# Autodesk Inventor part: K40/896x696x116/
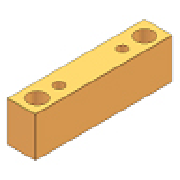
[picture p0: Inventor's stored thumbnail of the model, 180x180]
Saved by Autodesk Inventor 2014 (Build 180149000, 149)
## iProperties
Created: 2009-11
Part Number: K40/896x696x116/
Material: DIN 1.1730
Description: Spacer Block
Document SubType Name: Modeling
Designer: gaom
Standard Revision: 1
Manufacturer: HASCO
Language: en-US
Size Designation: 896x696x116/
Categories: <MemberInstance><Categories><Category DisplayName="Mold" InternalName="349578f2-f4d4-4954-8c09-8e99297a61c0" Mnemonic="MOLD"><Category DisplayName="Mold Plates"
Density: 7.82 g/cm^3
Appearance: Orange (Pale)
IsCustomPart: 1
Author: gaom
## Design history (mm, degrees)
sketch "Sketch1"
  geometry: L1 (-264, 448)-(-348, 448); L2 (-348, 448)-(-348, -448); L3 (-348, -448)-(-264, -448); L4 (-264, -448)-(-264, 448); L5 (348, 448)-(348, -448); L6 (264, -448)-(264, 448); L7 (264, 448)-(348, 448); L8 (264, -448)-(348, -448); 7 further points
  constraints: 16 end point, 3 parallel, 2 horizontal alignment, 2 midpoint, 2 perpendicular, 1 horizontal, 1 vertical
  dimensions: "d85" = 896 distance between parallel lines of L3 L1 (= L); "d86" = 84 distance between parallel lines of L4 L2 (= W_); "d88" = 84 distance between parallel lines of L5 L6 (= W_); "d89" = 348 distance from line of point (0, 0) L2 (= 0.5 x M_W); "d93" = 896 distance between parallel lines of L8 L7 (= L); "d94" = 348 distance from line of point (0, 0) L5 (= 0.5 x M_W); "d98" = 337 vertical distance of point (-296, 337) point (0, 0) (= 0.5 x S1_L); "d100" = 296 horizontal distance of point (-296, 337) point (0, 0) (= 0.5 x S1_W); "d101" = 296 horizontal distance of point (296, 337) point (0, 0) (= 0.5 x S1_W); "d102" = 337 vertical distance of point (0, 0) point (296, 337) (= 0.5 x S1_L); "d103" = 296 horizontal distance of point (-296, 396) point (0, 0) (= 0.5 x LS_W); "d105" = 396 vertical distance of point (-296, 396) point (0, 0) (= 0.5 x LS_L); "d106" = 296 horizontal distance of point (0, 0) point (296, 396) (= 0.5 x LS_W); "d107" = 396 vertical distance of point (296, 396) point (0, 0) (= 0.5 x LS_L)
extrude "Extrusion1" new body sketch "Sketch1" distance "d20" = 116 (= H_); taper "d30" = 0 deg
extrude "Extrusion2" join sketch "Sketch1" distance "d95" = 116 (= H_); taper "d96" = 0 deg
body "Solid1"
hole "Hole1" sketch "Sketch1" diameter "d129" = 22 (= S1_d1); stored, may be unused: countersink angle "d133" = 90 deg, drill point angle "d135" = 0 deg; dims "d130" = 6, "d131" = 4, "d132" = 2, "d134" = 116 (= H_)
pattern_linear "Rectangular Pattern1" dims "d156" = 674 (computed from S1_L, Ns)
hole "Hole2" sketch "Sketch1" diameter "d108" = 54 (= LS_d); stored, may be unused: countersink angle "d112" = 90 deg, drill point angle "d114" = 0 deg; dims "d109" = 6, "d110" = 4, "d111" = 2, "d113" = 116 (= H_)
pattern_linear "Rectangular Pattern2" dims "d138" = 792 (computed from LS_L, Nl)
hole "Hole3" sketch "Sketch1" diameter "d122" = 22 (= S1_d1); stored, may be unused: countersink angle "d126" = 90 deg, drill point angle "d128" = 0 deg; dims "d123" = 6, "d124" = 4, "d125" = 2, "d127" = 116 (= H_)
pattern_linear "Rectangular Pattern3" dims "d153" = 674 (computed from S1_L, Ns)
hole "Hole4" sketch "Sketch1" diameter "d115" = 54 (= LS_d); stored, may be unused: countersink angle "d119" = 90 deg, drill point angle "d121" = 0 deg; dims "d116" = 6, "d117" = 4, "d118" = 2, "d120" = 116 (= H_)
pattern_linear "Rectangular Pattern4" dims "d150" = 792 (computed from LS_L, Nl)
chamfer "Chamfer1" distance "d82" = 0.5; stored, may be unused: second distance "d83" = 2, angle "d84" = 45 deg
chamfer "Chamfer2" distance "d157" = 0.5; stored, may be unused: second distance "d158" = 2, angle "d159" = 45 deg
workplane "Work Plane1"
workplane "Work Plane2"
other parameters: "L" = 896 [user parameter; used in 2 equation terms], "W_" = 84 [user parameter; used in 2 equation terms], "H_" = 116 [user parameter; used in 7 equation terms], "M_W" = 696 [user parameter; used in 2 equation terms], "S1_L" = 674 [user parameter; used in 4 equation terms], "S1_W" = 592 [user parameter; used in 2 equation terms], "S1_d1" = 22 [user parameter; used in 2 equation terms], "LS_L" = 792 [user parameter; used in 4 equation terms], "LS_W" = 592 [user parameter; used in 2 equation terms], "LS_d" = 54 [user parameter; used in 2 equation terms], "d161" = 0, "d162" = 116 (= H_)
